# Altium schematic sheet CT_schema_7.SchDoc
size 277 x 170 mm
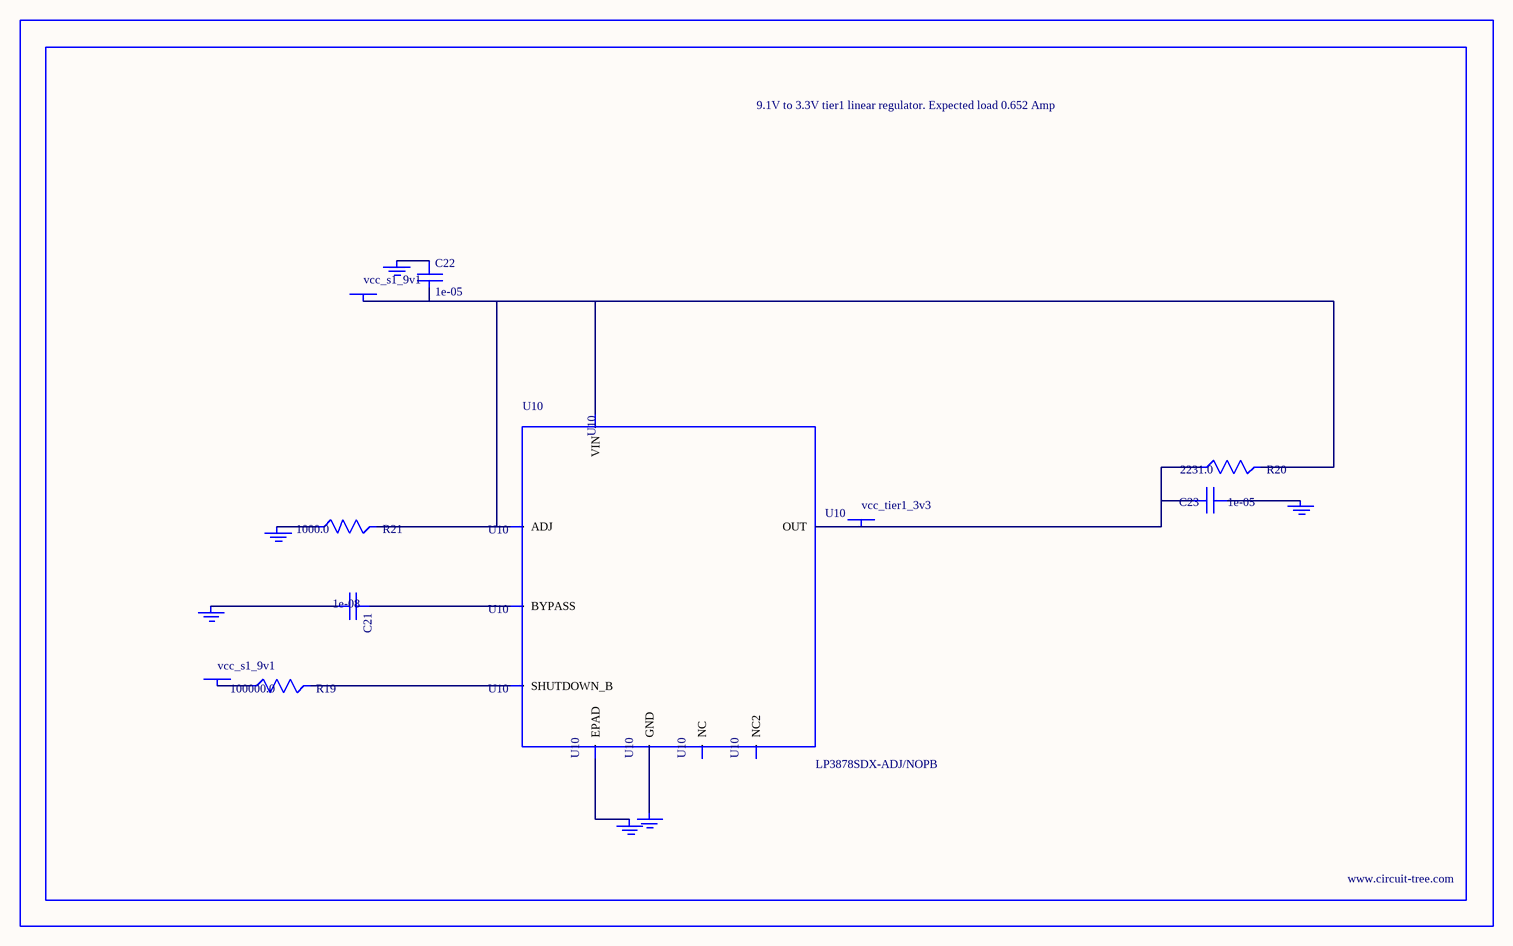
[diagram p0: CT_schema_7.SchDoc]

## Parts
BORDER6  (no value)
C21  1e-08  [C0402]
C22  1e-05  [C1206]
C23  1e-05  [C1210]
GND_INSTANCE_6_0  (no value)
GND_INSTANCE_6_1  (no value)
GND_INSTANCE_6_2  (no value)
GND_INSTANCE_6_3  (no value)
GND_INSTANCE_6_4  (no value)
GND_INSTANCE_6_5  (no value)
POWER_INSTANCE_6_0  vcc_s1_9v1
POWER_INSTANCE_6_1  vcc_s1_9v1
POWER_INSTANCE_6_2  vcc_tier1_3v3
R19  100000.0  [R0603]
R20  2231.0  [R0603]
R21  1000.0  [R0603]
U10  LP3878SDX-ADJ/NOPB  [WSON-8]

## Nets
NetC21_1: C21.1 U10.1(BYPASS)
NetC21_2: C21.2 GND_INSTANCE_6_0.0(GND)
NetC22_1: C22.1 GND_INSTANCE_6_1.0(GND)
NetC22_2: C22.2 POWER_INSTANCE_6_0.0(PWR) R20.2 R21.2 U10.4(VIN) U10.6(ADJ)
NetC23_1: C23.1 GND_INSTANCE_6_2.0(GND)
NetC23_2: C23.2 POWER_INSTANCE_6_2.0(PWR) R20.1 U10.5(OUT)
NetGND_INSTANCE_6_3_0: GND_INSTANCE_6_3.0(GND) R21.1
NetGND_INSTANCE_6_4_0: GND_INSTANCE_6_4.0(GND) U10.PAD(EPAD)
NetGND_INSTANCE_6_5_0: GND_INSTANCE_6_5.0(GND) U10.3(GND)
NetPOWER_INSTANCE_6_1_0: POWER_INSTANCE_6_1.0(PWR) R19.1
NetR19_2: R19.2 U10.8(SHUTDOWN_B)

Not connected (* = marked no-connect by the designer): U10 2(NC) 7(NC2)

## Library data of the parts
BORDER6 = BORDER_PAGE6
C21 = C0402C103K3RAC
C22 = C1206C106K3RACTU
C23 = GRM32DR61E106MA12L
GND_INSTANCE_6_0-GND_INSTANCE_6_5 = GND
POWER_INSTANCE_6_0-POWER_INSTANCE_6_2 = PWR
R19 = RC0603JR-07100KL
R20 = R20
R21 = RC0603JR-071KL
